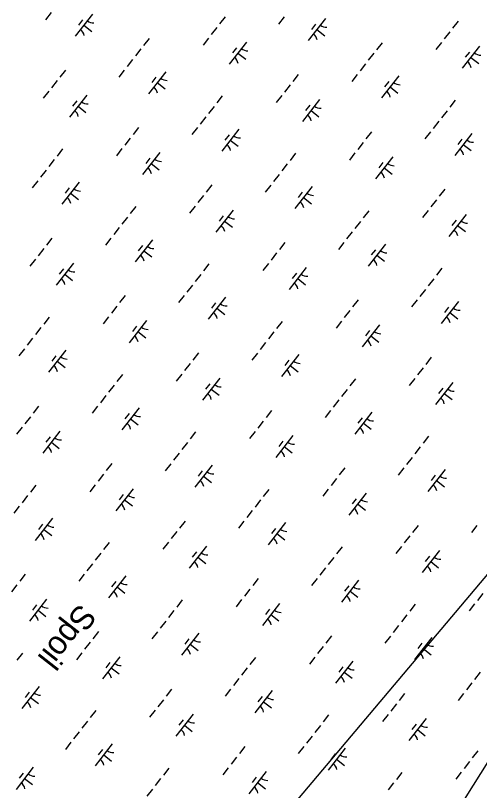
# Model space of a CAD drawing. Extents: x 3896831 to 3918110, y 171006 to 193349.
# Drawn here: x 3903389 to 3904219, y 178019 to 179403 of the extents above; entities that cross this region are included whole.
import ezdxf

# ---------------------------------------------------------------- set-up
doc = ezdxf.new("R2010")
doc.units = 0
for name, color, linetype in [('V-CHAN-SPOL', 7, 'Continuous'), ('V-UTIL-LINE', 7, 'Continuous'), ('V-WETL-SWMP', 7, 'Continuous')]:
    doc.layers.add(name, color=color, linetype=linetype)

msp = doc.modelspace()

# ---------------------------------------------------------------- linework, layer by layer
at = {"layer": 'V-UTIL-LINE'}
for points in [[(3911670.5, 187980.3), (3909726.1, 186106.6), (3909690.7, 186047.7), (3909490.4, 185423.1), (3908571.2, 184256.5), (3908123.4, 183643.7), (3907157.1, 182394.6), (3906544.4, 181593.3), (3906120.1, 181051.2), (3905460.2, 180002.4), (3904670.7, 178765.1), (3903951.9, 177622.1), (3903445.2, 176832.5), (3902962, 176054.8), (3902856, 175866.2)], [(3902278.5, 176090.1), (3904647.1, 178894.7), (3905719.5, 180143.9), (3906520.8, 181098.4), (3907322.1, 182041.1), (3907534.2, 182300.3), (3908041, 182924.9), (3909514, 184881.1), (3910138.5, 185694.2), (3909821.8, 185935.5), (3909829.3, 185945.1), (3909882.7, 185907)]]:
    msp.add_lwpolyline(points, dxfattribs=at)
at = {"layer": 'V-WETL-SWMP'}
for p, q in [((3903452.7, 179408.4), (3903442.8, 179395.8)), ((3903526.8, 179405.7), (3903496, 179366.3)), ((3903763.9, 179400.8), (3903754, 179388.2)), ((3903869.3, 179400.7), (3903859.5, 179388.1)), ((3903509, 179395.5), (3903501.6, 179386)), ((3903511.4, 179386), (3903525.6, 179374.9)), ((3903943.5, 179398), (3903912.6, 179358.6)), ((3903925.7, 179387.8), (3903918.3, 179378.3)), ((3904180.5, 179393.1), (3904170.6, 179380.5)), ((3903749.1, 179381.9), (3903739.2, 179369.3)), ((3903928, 179378.3), (3903942.2, 179367.2)), ((3904165.7, 179374.2), (3904155.8, 179361.6)), ((3903628, 179362.5), (3903618.2, 179349.9)), ((3903734.3, 179363), (3903724.4, 179350.4)), ((3903802.1, 179356), (3903771.2, 179316.7)), ((3903784.3, 179345.8), (3903776.9, 179336.4)), ((3904044.7, 179354.8), (3904034.8, 179342.2)), ((3904150.9, 179355.3), (3904141, 179342.7)), ((3904218.7, 179348.3), (3904187.9, 179309)), ((3903613.2, 179343.6), (3903603.4, 179331)), ((3903786.7, 179336.3), (3903800.8, 179325.2)), ((3904029.9, 179335.9), (3904020, 179323.3)), ((3904200.9, 179338.1), (3904193.5, 179328.7)), ((3903598.4, 179324.7), (3903588.5, 179312.1)), ((3904015.1, 179317), (3904005.2, 179304.4)), ((3904203.3, 179328.6), (3904217.5, 179317.5)), ((3903478.2, 179305.9), (3903468.3, 179293.3)), ((3903583.6, 179305.8), (3903573.7, 179293.2)), ((3903657.7, 179303), (3903626.9, 179263.7)), ((3903640, 179292.9), (3903632.6, 179283.4)), ((3903894.8, 179298.2), (3903884.9, 179285.6)), ((3904000.3, 179298.1), (3903990.4, 179285.5)), ((3904074.4, 179295.3), (3904043.5, 179256)), ((3903463.3, 179287), (3903453.5, 179274.4)), ((3903642.3, 179283.4), (3903656.5, 179272.3)), ((3903880, 179279.3), (3903870.1, 179266.7)), ((3904056.6, 179285.2), (3904049.2, 179275.7)), ((3904059, 179275.7), (3904073.1, 179264.6)), ((3903448.5, 179268.1), (3903438.7, 179255.5)), ((3903516.4, 179261.1), (3903485.5, 179221.7)), ((3903498.6, 179250.9), (3903491.2, 179241.5)), ((3903758.9, 179259.8), (3903749.1, 179247.2)), ((3903865.2, 179260.4), (3903855.3, 179247.8)), ((3903933, 179253.4), (3903902.2, 179214)), ((3904175.6, 179252.1), (3904165.7, 179239.5)), ((3903500.9, 179241.4), (3903515.1, 179230.3)), ((3903744.1, 179241), (3903734.3, 179228.4)), ((3903915.2, 179243.2), (3903907.8, 179233.8)), ((3903917.6, 179233.7), (3903931.7, 179222.6)), ((3903729.3, 179222.1), (3903719.5, 179209.5)), ((3904160.8, 179233.3), (3904150.9, 179220.7)), ((3904146, 179214.4), (3904136.1, 179201.8)), ((3903609.1, 179203.3), (3903599.2, 179190.7)), ((3903714.5, 179203.2), (3903704.7, 179190.6)), ((3903788.7, 179200.4), (3903757.8, 179161.1)), ((3904025.7, 179195.6), (3904015.8, 179183)), ((3904131.2, 179195.5), (3904121.3, 179182.9)), ((3904205.3, 179192.7), (3904174.5, 179153.4)), ((3903594.3, 179184.4), (3903584.4, 179171.8)), ((3903770.9, 179190.2), (3903763.5, 179180.8)), ((3903773.2, 179180.8), (3903787.4, 179169.7)), ((3904187.5, 179182.5), (3904180.1, 179173.1)), ((3903473.2, 179164.9), (3903463.4, 179152.3)), ((3903579.5, 179165.5), (3903569.6, 179152.9)), ((3904010.9, 179176.7), (3904001, 179164.1)), ((3904189.9, 179173.1), (3904204.1, 179162)), ((3903647.3, 179158.5), (3903616.4, 179119.1)), ((3903889.9, 179157.2), (3903880, 179144.6)), ((3903996.1, 179157.8), (3903986.2, 179145.2)), ((3904063.9, 179150.8), (3904033.1, 179111.4)), ((3903458.4, 179146), (3903448.5, 179133.5)), ((3903629.5, 179148.3), (3903622.1, 179138.9)), ((3903631.9, 179138.8), (3903646, 179127.7)), ((3903875.1, 179138.3), (3903865.2, 179125.8)), ((3904046.1, 179140.6), (3904038.7, 179131.2)), ((3903443.6, 179127.2), (3903433.7, 179114.6)), ((3904048.5, 179131.1), (3904062.7, 179120)), ((3903860.3, 179119.5), (3903850.4, 179106.9)), ((3903428.8, 179108.3), (3903418.9, 179095.7)), ((3903502.9, 179105.5), (3903472.1, 179066.2)), ((3903485.1, 179095.3), (3903477.7, 179085.9)), ((3903740, 179100.7), (3903730.1, 179088.1)), ((3903845.5, 179100.6), (3903835.6, 179088)), ((3903919.6, 179097.8), (3903888.7, 179058.5)), ((3903487.5, 179085.9), (3903501.7, 179074.7)), ((3903725.2, 179081.8), (3903715.3, 179069.2)), ((3903901.8, 179087.6), (3903894.4, 179078.2)), ((3904156.6, 179093), (3904146.8, 179080.4)), ((3903904.2, 179078.2), (3903918.3, 179067)), ((3904141.8, 179074.1), (3904132, 179061.5)), ((3903604.1, 179062.3), (3903594.3, 179049.7)), ((3903710.4, 179062.9), (3903700.5, 179050.3)), ((3903778.2, 179055.9), (3903747.4, 179016.5)), ((3904020.8, 179054.6), (3904010.9, 179042)), ((3904127, 179055.2), (3904117.2, 179042.6)), ((3903589.3, 179043.4), (3903579.5, 179030.8)), ((3903760.4, 179045.7), (3903753, 179036.2)), ((3904194.8, 179048.2), (3904164, 179008.8)), ((3903762.8, 179036.2), (3903776.9, 179025.1)), ((3904006, 179035.7), (3903996.1, 179023.1)), ((3904177, 179038), (3904169.6, 179028.5)), ((3904179.4, 179028.5), (3904193.6, 179017.4)), ((3903574.5, 179024.5), (3903564.7, 179012)), ((3903991.2, 179016.8), (3903981.3, 179004.3)), ((3903454.3, 179005.8), (3903444.4, 178993.2)), ((3903559.7, 179005.7), (3903549.9, 178993.1)), ((3903633.9, 179002.9), (3903603, 178963.6)), ((3903439.5, 178986.9), (3903429.6, 178974.3)), ((3903616.1, 178992.7), (3903608.7, 178983.3)), ((3903870.9, 178998.1), (3903861, 178985.5)), ((3903976.4, 178998), (3903966.5, 178985.4)), ((3904050.5, 178995.2), (3904019.7, 178955.9)), ((3904032.7, 178985), (3904025.3, 178975.6)), ((3903618.4, 178983.2), (3903632.6, 178972.1)), ((3903856.1, 178979.2), (3903846.2, 178966.6)), ((3904035.1, 178975.5), (3904049.2, 178964.4)), ((3903424.7, 178968), (3903414.8, 178955.4)), ((3903492.5, 178961), (3903461.6, 178921.6)), ((3903735.1, 178959.7), (3903725.2, 178947.1)), ((3903841.3, 178960.3), (3903831.4, 178947.7)), ((3903474.7, 178950.8), (3903467.3, 178941.3)), ((3903909.1, 178953.3), (3903878.3, 178913.9)), ((3903891.3, 178943.1), (3903883.9, 178933.6)), ((3904151.7, 178952), (3904141.8, 178939.4)), ((3903477, 178941.3), (3903491.2, 178930.2)), ((3903720.3, 178940.8), (3903710.4, 178928.2)), ((3903893.7, 178933.6), (3903907.9, 178922.5)), ((3904136.9, 178933.1), (3904127, 178920.5)), ((3903705.4, 178921.9), (3903695.6, 178909.3)), ((3903585.2, 178903.2), (3903575.3, 178890.6)), ((3903690.6, 178903), (3903680.8, 178890.5)), ((3904122.1, 178914.2), (3904112.2, 178901.6)), ((3903764.8, 178900.3), (3903733.9, 178861)), ((3903747, 178890.1), (3903739.6, 178880.7)), ((3904001.8, 178895.5), (3903992, 178882.9)), ((3904107.3, 178895.3), (3904097.4, 178882.8)), ((3904181.4, 178892.6), (3904150.6, 178853.3)), ((3903570.4, 178884.3), (3903560.5, 178871.7)), ((3903749.4, 178880.6), (3903763.5, 178869.5)), ((3903987, 178876.6), (3903977.1, 178864)), ((3904163.6, 178882.4), (3904156.2, 178873)), ((3903449.3, 178864.8), (3903439.5, 178852.2)), ((3903555.6, 178865.4), (3903545.7, 178852.8)), ((3904166, 178872.9), (3904180.2, 178861.8)), ((3903623.4, 178858.4), (3903592.5, 178819)), ((3903605.6, 178848.2), (3903598.2, 178838.7)), ((3903866, 178857.1), (3903856.1, 178844.5)), ((3903972.2, 178857.7), (3903962.3, 178845.1)), ((3904040, 178850.7), (3904009.2, 178811.3)), ((3903434.5, 178845.9), (3903424.7, 178833.3)), ((3903608, 178838.7), (3903622.1, 178827.6)), ((3903851.2, 178838.2), (3903841.3, 178825.6)), ((3904022.2, 178840.5), (3904014.8, 178831)), ((3903419.7, 178827), (3903409.9, 178814.4)), ((3903836.4, 178819.3), (3903826.5, 178806.7)), ((3904024.6, 178831), (3904038.8, 178819.9)), ((3903404.9, 178808.1), (3903395, 178795.5)), ((3903479.1, 178805.4), (3903448.2, 178766.1)), ((3903461.3, 178795.2), (3903453.9, 178785.8)), ((3903716.1, 178800.6), (3903706.2, 178788)), ((3903821.6, 178800.4), (3903811.7, 178787.8)), ((3903895.7, 178797.7), (3903864.9, 178758.4)), ((3904132.7, 178792.9), (3904122.9, 178780.3)), ((3903463.6, 178785.7), (3903477.8, 178774.6)), ((3903701.3, 178781.7), (3903691.4, 178769.1)), ((3903877.9, 178787.5), (3903870.5, 178778.1)), ((3903880.3, 178778), (3903894.4, 178766.9)), ((3904117.9, 178774), (3904108.1, 178761.4)), ((3903580.3, 178762.2), (3903570.4, 178749.6)), ((3903686.5, 178762.8), (3903676.6, 178750.2)), ((3903754.3, 178755.8), (3903723.5, 178716.4)), ((3903996.9, 178754.5), (3903987, 178741.9)), ((3904103.1, 178755.1), (3904093.3, 178742.5)), ((3903565.4, 178743.3), (3903555.6, 178730.7)), ((3903736.5, 178745.6), (3903729.1, 178736.1)), ((3903738.9, 178736.1), (3903753.1, 178725)), ((3903982.1, 178735.6), (3903972.2, 178723)), ((3904170.9, 178748.1), (3904140.1, 178708.7)), ((3904153.2, 178737.9), (3904145.8, 178728.4)), ((3903550.6, 178724.4), (3903540.8, 178711.8)), ((3904155.5, 178728.4), (3904169.7, 178717.3)), ((3903967.3, 178716.7), (3903957.4, 178704.1)), ((3903430.4, 178705.7), (3903420.5, 178693.1)), ((3903535.8, 178705.5), (3903526, 178692.9)), ((3903610, 178702.8), (3903579.1, 178663.4)), ((3903847, 178698), (3903837.1, 178685.4)), ((3903952.5, 178697.8), (3903942.6, 178685.2)), ((3904026.6, 178695.1), (3903995.8, 178655.7)), ((3903415.6, 178686.8), (3903405.7, 178674.2)), ((3903592.2, 178692.6), (3903584.8, 178683.2)), ((3903594.6, 178683.1), (3903608.7, 178672)), ((3904008.8, 178684.9), (3904001.4, 178675.5)), ((3903400.8, 178667.9), (3903390.9, 178655.3)), ((3903832.2, 178679.1), (3903822.3, 178666.5)), ((3904011.2, 178675.4), (3904025.4, 178664.3)), ((3903468.6, 178660.8), (3903437.7, 178621.5)), ((3903711.2, 178659.6), (3903701.3, 178647)), ((3903817.4, 178660.2), (3903807.5, 178647.6)), ((3903885.2, 178653.1), (3903854.4, 178613.8)), ((3903450.8, 178650.7), (3903443.4, 178641.2)), ((3903453.2, 178641.2), (3903467.3, 178630.1)), ((3903696.4, 178640.7), (3903686.5, 178628.1)), ((3903867.4, 178643), (3903860, 178633.5)), ((3904127.8, 178651.9), (3904117.9, 178639.3)), ((3903869.8, 178633.5), (3903884, 178622.4)), ((3904113, 178633), (3904103.1, 178620.4)), ((3903681.6, 178621.8), (3903671.7, 178609.2)), ((3904098.2, 178614.1), (3904088.3, 178601.5)), ((3903561.3, 178603.1), (3903551.4, 178590.5)), ((3903666.8, 178602.9), (3903656.9, 178590.3)), ((3903740.9, 178600.2), (3903710, 178560.8)), ((3903546.5, 178584.2), (3903536.6, 178571.6)), ((3903723.1, 178590), (3903715.7, 178580.5)), ((3903977.9, 178595.4), (3903968.1, 178582.8)), ((3904083.4, 178595.2), (3904073.5, 178582.6)), ((3904157.5, 178592.5), (3904126.7, 178553.1)), ((3903725.5, 178580.5), (3903739.6, 178569.4)), ((3903963.1, 178576.5), (3903953.3, 178563.9)), ((3904139.7, 178582.3), (3904132.3, 178572.8)), ((3904142.1, 178572.8), (3904156.3, 178561.7)), ((3903425.4, 178564.7), (3903415.6, 178552.1)), ((3903531.7, 178565.3), (3903521.8, 178552.7)), ((3903599.5, 178558.2), (3903568.7, 178518.9)), ((3903842.1, 178557), (3903832.2, 178544.4)), ((3903948.3, 178557.6), (3903938.5, 178545)), ((3903410.6, 178545.8), (3903400.8, 178533.2)), ((3903581.7, 178548), (3903574.3, 178538.6)), ((3904016.1, 178550.5), (3903985.3, 178511.2)), ((3903584.1, 178538.6), (3903598.2, 178527.5)), ((3903827.3, 178538.1), (3903817.4, 178525.5)), ((3903998.3, 178540.3), (3903990.9, 178530.9)), ((3904000.7, 178530.9), (3904014.9, 178519.8)), ((3903395.8, 178526.9), (3903386, 178514.3)), ((3903812.5, 178519.2), (3903802.6, 178506.6)), ((3903455.2, 178505.3), (3903424.3, 178465.9)), ((3903692.2, 178500.4), (3903682.3, 178487.9)), ((3903797.7, 178500.3), (3903787.8, 178487.7)), ((3903437.4, 178495.1), (3903430, 178485.6)), ((3903871.8, 178497.6), (3903841, 178458.2)), ((3903854, 178487.4), (3903846.6, 178477.9)), ((3904108.9, 178492.7), (3904099, 178480.2)), ((3904214.3, 178492.6), (3904204.4, 178480)), ((3903439.7, 178485.6), (3903453.9, 178474.5)), ((3903677.4, 178481.6), (3903667.5, 178469)), ((3903856.4, 178477.9), (3903870.6, 178466.8)), ((3904094.1, 178473.9), (3904084.2, 178461.3)), ((3903556.4, 178462.1), (3903546.5, 178449.5)), ((3903662.6, 178462.7), (3903652.7, 178450.1)), ((3903730.4, 178455.6), (3903699.6, 178416.3)), ((3903712.6, 178445.4), (3903705.2, 178436)), ((3903973, 178454.4), (3903963.1, 178441.8)), ((3904079.2, 178455), (3904069.4, 178442.4)), ((3904147.1, 178447.9), (3904116.2, 178408.6)), ((3903541.6, 178443.2), (3903531.7, 178430.6)), ((3903715, 178436), (3903729.2, 178424.8)), ((3903958.2, 178435.5), (3903948.3, 178422.9)), ((3904129.3, 178437.7), (3904121.9, 178428.3)), ((3903526.8, 178424.3), (3903516.9, 178411.7)), ((3904131.6, 178428.3), (3904145.8, 178417.1)), ((3903406.5, 178405.5), (3903396.6, 178392.9)), ((3903512, 178405.4), (3903502.1, 178392.8)), ((3903943.4, 178416.6), (3903933.5, 178404)), ((3903586.1, 178402.7), (3903555.2, 178363.3)), ((3903568.3, 178392.5), (3903560.9, 178383)), ((3903823.1, 178397.8), (3903813.3, 178385.2)), ((3903928.6, 178397.7), (3903918.7, 178385.1)), ((3904002.7, 178395), (3903971.9, 178355.6)), ((3903391.7, 178386.6), (3903381.8, 178374.1)), ((3903570.7, 178383), (3903584.8, 178371.9)), ((3903808.3, 178378.9), (3903798.5, 178366.4)), ((3903984.9, 178384.8), (3903977.5, 178375.3)), ((3903987.3, 178375.3), (3904001.5, 178364.2)), ((3904225, 178371.2), (3904215.1, 178358.7)), ((3903444.7, 178360.7), (3903413.9, 178321.4)), ((3903426.9, 178350.5), (3903419.5, 178341.1)), ((3903687.3, 178359.5), (3903677.4, 178346.9)), ((3903793.5, 178360.1), (3903783.7, 178347.5)), ((3903861.3, 178353), (3903830.5, 178313.7)), ((3904103.9, 178351.8), (3904094.1, 178339.2)), ((3904210.2, 178352.4), (3904200.3, 178339.8)), ((3903429.3, 178341), (3903443.4, 178329.9)), ((3903672.5, 178340.6), (3903662.6, 178328)), ((3903843.5, 178342.8), (3903836.1, 178333.4)), ((3903657.7, 178321.7), (3903647.8, 178309.1)), ((3903845.9, 178333.3), (3903860.1, 178322.2)), ((3904089.1, 178332.9), (3904079.3, 178320.3)), ((3904074.3, 178314), (3904064.4, 178301.4)), ((3903537.4, 178302.9), (3903527.5, 178290.3)), ((3903642.9, 178302.8), (3903633, 178290.2)), ((3903717, 178300.1), (3903686.2, 178260.7)), ((3903954, 178295.2), (3903944.2, 178282.6)), ((3904059.5, 178295.1), (3904049.6, 178282.5)), ((3903522.6, 178284), (3903512.7, 178271.4)), ((3903699.2, 178289.9), (3903691.8, 178280.4)), ((3903701.6, 178280.4), (3903715.7, 178269.3)), ((3904133.6, 178292.4), (3904102.8, 178253)), ((3904115.9, 178282.2), (3904108.5, 178272.7)), ((3903507.8, 178265.1), (3903497.9, 178252.6)), ((3903939.2, 178276.3), (3903929.4, 178263.7)), ((3904118.2, 178272.7), (3904132.4, 178261.6)), ((3903401.6, 178264.6), (3903391.7, 178252)), ((3903575.6, 178258.1), (3903544.8, 178218.8)), ((3903818.2, 178256.9), (3903808.3, 178244.3)), ((3903924.4, 178257.4), (3903914.6, 178244.9)), ((3903557.8, 178247.9), (3903550.4, 178238.5)), ((3903560.2, 178238.4), (3903574.4, 178227.3)), ((3903803.4, 178238), (3903793.5, 178225.4)), ((3903992.3, 178250.4), (3903961.4, 178211.1)), ((3903974.5, 178240.2), (3903967.1, 178230.8)), ((3903976.8, 178230.7), (3903991, 178219.6)), ((3904220, 178230.3), (3904210.2, 178217.7)), ((3903788.6, 178219.1), (3903778.7, 178206.5)), ((3904205.2, 178211.4), (3904195.4, 178198.8)), ((3903431.3, 178205.2), (3903400.4, 178165.8)), ((3903668.3, 178200.3), (3903658.5, 178187.7)), ((3903773.8, 178200.2), (3903763.9, 178187.6)), ((3903847.9, 178197.5), (3903817.1, 178158.1)), ((3903413.5, 178195), (3903406.1, 178185.5)), ((3903415.9, 178185.5), (3903430, 178174.4)), ((3903830.1, 178187.3), (3903822.7, 178177.8)), ((3904085, 178192.6), (3904075.1, 178180)), ((3904190.4, 178192.5), (3904180.6, 178179.9)), ((3903653.5, 178181.4), (3903643.7, 178168.8)), ((3903832.5, 178177.8), (3903846.7, 178166.7)), ((3904070.2, 178173.7), (3904060.3, 178161.1)), ((3903532.5, 178161.9), (3903522.6, 178149.4)), ((3903638.7, 178162.5), (3903628.8, 178149.9)), ((3903706.5, 178155.5), (3903675.7, 178116.2)), ((3903949.1, 178154.2), (3903939.3, 178141.7)), ((3904055.4, 178154.8), (3904045.5, 178142.2)), ((3903517.7, 178143.1), (3903507.8, 178130.5)), ((3903688.7, 178145.3), (3903681.3, 178135.9)), ((3904123.2, 178147.8), (3904092.3, 178108.5)), ((3903691.1, 178135.8), (3903705.3, 178124.7)), ((3903934.3, 178135.4), (3903924.4, 178122.8)), ((3904105.4, 178137.6), (3904098, 178128.2)), ((3904107.8, 178128.1), (3904121.9, 178117)), ((3903502.9, 178124.2), (3903493, 178111.6)), ((3903919.5, 178116.5), (3903909.6, 178103.9)), ((3903488.1, 178105.3), (3903478.2, 178092.7)), ((3903562.2, 178102.5), (3903531.4, 178063.2)), ((3903544.4, 178092.3), (3903537, 178082.9)), ((3903799.2, 178097.7), (3903789.4, 178085.1)), ((3903904.7, 178097.6), (3903894.8, 178085)), ((3903978.8, 178094.8), (3903948, 178055.5)), ((3904215.9, 178090), (3904206, 178077.4)), ((3903546.8, 178082.9), (3903560.9, 178071.8)), ((3903784.4, 178078.8), (3903774.6, 178066.2)), ((3903961, 178084.6), (3903953.6, 178075.2)), ((3903963.4, 178075.2), (3903977.6, 178064.1)), ((3904201.1, 178071.1), (3904191.2, 178058.5)), ((3903420.8, 178060.6), (3903390, 178021.2)), ((3903663.4, 178059.3), (3903653.5, 178046.7)), ((3903769.6, 178059.9), (3903759.8, 178047.3)), ((3903403, 178050.4), (3903395.6, 178041)), ((3903837.4, 178052.9), (3903806.6, 178013.5)), ((3904080, 178051.6), (3904070.2, 178039)), ((3904186.3, 178052.2), (3904176.4, 178039.6)), ((3903405.4, 178040.9), (3903419.6, 178029.8)), ((3903648.6, 178040.5), (3903638.7, 178027.9)), ((3903819.7, 178042.7), (3903812.3, 178033.3)), ((3903822, 178033.2), (3903836.2, 178022.1)), ((3904065.2, 178032.8), (3904055.4, 178020.2)), ((3903633.8, 178021.6), (3903623.9, 178009))]:
    msp.add_line(p, q, dxfattribs=at)
for centre, start, end in [((3903528.6, 179407.6), 231.1403, 272.6839), ((3903945.3, 179399.9), 231.1403, 272.6839), ((3903494.6, 179364.1), 11.1403, 52.6839), ((3903911.2, 179356.4), 11.1403, 52.6839), ((3903803.9, 179357.9), 231.1403, 272.6839), ((3904220.5, 179350.2), 231.1403, 272.6839), ((3903769.8, 179314.4), 11.1403, 52.6839), ((3904186.5, 179306.7), 11.1403, 52.6839), ((3903659.6, 179305), 231.1403, 272.6839), ((3903625.5, 179261.5), 11.1403, 52.6839), ((3904076.2, 179297.3), 231.1403, 272.6839), ((3904042.1, 179253.8), 11.1403, 52.6839), ((3903518.2, 179263), 231.1403, 272.6839), ((3903934.8, 179255.3), 231.1403, 272.6839), ((3903484.1, 179219.5), 11.1403, 52.6839), ((3903900.7, 179211.8), 11.1403, 52.6839), ((3903790.5, 179202.4), 231.1403, 272.6839), ((3904207.1, 179194.7), 231.1403, 272.6839), ((3903756.4, 179158.9), 11.1403, 52.6839), ((3904173, 179151.2), 11.1403, 52.6839), ((3903649.1, 179160.4), 231.1403, 272.6839), ((3904065.7, 179152.7), 231.1403, 272.6839), ((3903615, 179116.9), 11.1403, 52.6839), ((3904031.6, 179109.2), 11.1403, 52.6839), ((3903504.7, 179107.4), 231.1403, 272.6839), ((3903921.4, 179099.7), 231.1403, 272.6839), ((3903470.7, 179064), 11.1403, 52.6839), ((3903887.3, 179056.3), 11.1403, 52.6839), ((3903780, 179057.8), 231.1403, 272.6839), ((3903745.9, 179014.3), 11.1403, 52.6839), ((3904196.6, 179050.1), 231.1403, 272.6839), ((3904162.6, 179006.6), 11.1403, 52.6839), ((3903635.7, 179004.8), 231.1403, 272.6839), ((3903601.6, 178961.4), 11.1403, 52.6839), ((3904052.3, 178997.1), 231.1403, 272.6839), ((3904018.2, 178953.7), 11.1403, 52.6839), ((3903494.3, 178962.9), 231.1403, 272.6839), ((3903460.2, 178919.4), 11.1403, 52.6839), ((3903910.9, 178955.2), 231.1403, 272.6839), ((3903876.8, 178911.7), 11.1403, 52.6839), ((3903766.6, 178902.2), 231.1403, 272.6839), ((3904183.2, 178894.5), 231.1403, 272.6839), ((3903732.5, 178858.7), 11.1403, 52.6839), ((3904149.1, 178851), 11.1403, 52.6839), ((3903625.2, 178860.3), 231.1403, 272.6839), ((3904041.8, 178852.6), 231.1403, 272.6839), ((3903591.1, 178816.8), 11.1403, 52.6839), ((3904007.8, 178809.1), 11.1403, 52.6839), ((3903480.9, 178807.3), 231.1403, 272.6839), ((3903446.8, 178763.8), 11.1403, 52.6839), ((3903897.5, 178799.6), 231.1403, 272.6839), ((3903863.4, 178756.1), 11.1403, 52.6839), ((3903756.1, 178757.7), 231.1403, 272.6839), ((3904172.8, 178750), 231.1403, 272.6839), ((3903722, 178714.2), 11.1403, 52.6839), ((3904138.7, 178706.5), 11.1403, 52.6839), ((3903611.8, 178704.7), 231.1403, 272.6839), ((3904028.4, 178697), 231.1403, 272.6839), ((3903577.7, 178661.2), 11.1403, 52.6839), ((3903994.3, 178653.5), 11.1403, 52.6839), ((3903470.4, 178662.8), 231.1403, 272.6839), ((3903887, 178655.1), 231.1403, 272.6839), ((3903436.3, 178619.3), 11.1403, 52.6839), ((3903853, 178611.6), 11.1403, 52.6839), ((3903742.7, 178602.1), 231.1403, 272.6839), ((3903708.6, 178558.6), 11.1403, 52.6839), ((3904159.3, 178594.4), 231.1403, 272.6839), ((3904125.3, 178550.9), 11.1403, 52.6839), ((3903601.3, 178560.2), 231.1403, 272.6839), ((3903567.2, 178516.7), 11.1403, 52.6839), ((3904017.9, 178552.5), 231.1403, 272.6839), ((3903983.9, 178509), 11.1403, 52.6839), ((3903457, 178507.2), 231.1403, 272.6839), ((3903422.9, 178463.7), 11.1403, 52.6839), ((3903873.6, 178499.5), 231.1403, 272.6839), ((3903839.5, 178456), 11.1403, 52.6839), ((3903732.2, 178457.5), 231.1403, 272.6839), ((3904148.9, 178449.8), 231.1403, 272.6839), ((3903698.1, 178414.1), 11.1403, 52.6839), ((3904114.8, 178406.4), 11.1403, 52.6839), ((3903587.9, 178404.6), 231.1403, 272.6839), ((3904004.5, 178396.9), 231.1403, 272.6839), ((3903553.8, 178361.1), 11.1403, 52.6839), ((3903970.5, 178353.4), 11.1403, 52.6839), ((3903446.5, 178362.6), 231.1403, 272.6839), ((3903863.1, 178354.9), 231.1403, 272.6839), ((3903412.4, 178319.2), 11.1403, 52.6839), ((3903829.1, 178311.5), 11.1403, 52.6839), ((3903718.8, 178302), 231.1403, 272.6839), ((3904135.5, 178294.3), 231.1403, 272.6839), ((3903684.7, 178258.5), 11.1403, 52.6839), ((3904101.4, 178250.8), 11.1403, 52.6839), ((3903577.4, 178260), 231.1403, 272.6839), ((3903994.1, 178252.3), 231.1403, 272.6839), ((3903543.3, 178216.5), 11.1403, 52.6839), ((3903960, 178208.8), 11.1403, 52.6839), ((3903433.1, 178207.1), 231.1403, 272.6839), ((3903849.7, 178199.4), 231.1403, 272.6839), ((3903399, 178163.6), 11.1403, 52.6839), ((3903815.6, 178155.9), 11.1403, 52.6839), ((3903708.3, 178157.4), 231.1403, 272.6839), ((3903674.3, 178113.9), 11.1403, 52.6839), ((3904125, 178149.7), 231.1403, 272.6839), ((3904090.9, 178106.2), 11.1403, 52.6839), ((3903564, 178104.5), 231.1403, 272.6839), ((3903529.9, 178061), 11.1403, 52.6839), ((3903980.6, 178096.8), 231.1403, 272.6839), ((3903946.6, 178053.3), 11.1403, 52.6839), ((3903422.6, 178062.5), 231.1403, 272.6839), ((3903388.5, 178019), 11.1403, 52.6839), ((3903839.3, 178054.8), 231.1403, 272.6839), ((3903805.2, 178011.3), 11.1403, 52.6839)]:
    msp.add_arc(centre, 17.6, start, end, dxfattribs=at)

# ---------------------------------------------------------------- texts
at = {"layer": 'V-CHAN-SPOL'}
msp.add_text('Spoil', height=42, rotation=231.9086, dxfattribs=at).set_placement((3903503.7, 178355.2))

doc.saveas('drawing.dxf')
